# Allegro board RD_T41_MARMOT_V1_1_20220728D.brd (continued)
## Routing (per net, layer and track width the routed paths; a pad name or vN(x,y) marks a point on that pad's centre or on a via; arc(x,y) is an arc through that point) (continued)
VBAT: length 41.4
  TOP w0.254: R296.1 88.84,60.12 U25.1
  TOP w0.508: U25.1 88.83,62.13 C205.1 88.82,62.3 R295.2 83.08,63.34 v1(81.29,65.13)
  BOTTOM w0.381: BAT1.1 80.82,78.29 85.24,73.87 85.24,70.07 84.32,69.15 82.9,69.15 81.7,67.95 81.7,65.54 v1(81.29,65.13)
  BOTTOM w0.508: U27.8 72.19,75.11 C211.1 73.44,77.42 R303.2 77.42,77.43 BAT1.1
VBUS_5V:
  vias: v1(47.01,7.7) v1(47,6.97) v1(47.7,7.71) v1(47.7,6.98)
VCC_1V8: length 151.4
  TOP w0.254: 29.24,74.63 28.59,73.98 C24.1 26.37,73.98 R13.2 ; v1(15.84,66.2) 15.65,66.2 U8.3 14.97,64.44 R33.1
  TOP w0.381: v1(74.44,53.51) 73.82,54.14 v1(73.82,60.28) ; R36.1 111.45,31.46 103.09,31.46 95.85,38.7 Q1.1 91.07,41.39 84.6,41.39 R37.2 79.78,40.45 78.94,41.29 78.94,46.36 v1(79.07,46.49)
  TOP w0.635: v1(51.22,61.22) 41.03,71.41 41.03,75.76 39.21,77.58 35.3,77.58 J6.1
  BOTTOM w0.254: J6.1 25.78,76.14 v1(15.84,66.2)
  BOTTOM w0.381: 78.96,46.49 77.49,46.49 75.83,48.15 R30.1
  BOTTOM w0.508: Q3.2 55.22,58.02 55.77,58.57 69.11,58.57 70.83,60.28 v1(73.82,60.28) ; v1(74.44,53.51) 75.84,53.51 76.35,53.01 76.35,49.2 78.96,46.58 78.96,46.49 v1(79.07,46.49)
  BOTTOM w0.635: v1(51.22,61.22) 50.9,60.89 50.9,59.83 53.17,57.56 C204.1 53.74,58.02 Q3.2
VCC_3V3: length 163
  TOP w0.254: v1(76.13,13.38) 76.51,13.77 R215.1 ; R290.1 v1(117.67,56.69) 115.46,58.9 ; v1(82.65,18.99) R222.1 82.65,19.61 R232.1 ; R7.2 28.03,65 C13.1 28.92,64.99 29.7,65.77 ; v1(45.79,73.09) 45.79,67.46 50.86,62.39 v1(51,62.39) ; R288.2 107.45,93.68 109.68,91.44 ; R227.1 v1(86.23,18.87) ; v1(114.68,87.75) 114.1,87.75 R249.2 v1(110.98,88.43) ; v1(95.27,64.33) 94.39,64.33 D21.1 94.48,63.33 v1(95.3,63.33) ; R204.1 57.81,13.35 v1(57.48,13.68) ; v1(23.28,64.54) 16.33,71.49 R304.1 13.77,71.5 R297.1 11.78,72.54 v1(11.78,76.92) ; R301.2 v1(11.82,80.08) ; FB14.2 v1(83.79,5.02) ; R289.1 v1(117.68,52.43) ; U22.14 v1(81.22,18.64)
  TOP w0.292: R192.2 v1(105.06,34.3)
  TOP w0.381: v1(14.57,18.82) 23.78,28.04 R107.2 ; FB16.2 v1(21.6,60.63) ; J26.1 v1(118.39,52.13) ; FB13.2 v1(5.03,18.09)
  TOP w0.508: v1(61.87,14.84) 61.75,14.84 60.89,15.7 R24.2
  BOTTOM w0.254: R281.1 51.79,56.14 50.86,57.06 50.86,58.48 50.02,59.32 50.02,61.41 v1(51,62.39) ; R163.2 59.4,76.35 63.18,72.58 R307.2 67.71,72.57 R306.2 67.71,70.85 68.6,69.97 R305.2 ; v1(11.82,80.08) 12.32,79.58 12.32,77.46 v1(11.78,76.92) ; R314.1 76.72,13.82 R234.1 ; R314.1 76.36,13.38 v1(76.13,13.38) ; R314.1 77.72,12.82 R316.1 ; v1(114.68,87.75) 115.27,87.16 R257.2
  BOTTOM w0.381: v1(61.87,14.84) 62,14.71 R201.2 ; v1(81.22,18.64) 81.22,18.19 C181.1 80.94,17.91 C180.1 ; v1(5.03,18.09) 13.84,18.09 v1(14.57,18.82) C110.1 14.57,18.1 U10.1 13.42,16.36 R99.1 ; v1(117.67,56.69) 117.68,56.69 v1(117.68,52.43) 117.98,52.13 v1(118.39,52.13) ; v1(57.48,13.68) 57.48,13.88 58.21,14.61 R73.2
  BOTTOM w0.508: v1(48.86,77.64) FB12.1 48.64,76.94 46.79,75.09 FB11.1 45.96,73.26 v1(45.79,73.09) ; R236.2 v1(85.12,18.3) ; R201.2 v1(61.08,14.12) ; R163.2 v1(58.35,78.1)
  vias: v1(29.2,31.41) v1(29.55,32.02) v1(29.98,31.42) v1(33.69,65.73) v1(34.23,65.11) v1(34.69,65.73) v1(79.84,81.75) v1(79.84,80.75) v1(80.84,81.75) v1(80.84,80.75) v1(107.71,89.39) v1(108.66,88.43) v1(112.53,33.56) v1(112.52,32.87) v1(112.89,60.66) v1(113.42,60.05) v1(113.89,60.66) v1(114.42,60.05)
VCC_5V: length 34.5
  TOP w0.254: v1(36.66,11.94) R106.2 v1(35.88,12.71) ; C7.1 30.6,86.2 R2.1 29.66,85.25 27.6,85.25
  TOP w0.381: R25.2 50.27,30.52 v1(50.27,15.33) ; v1(107.7,72.05) R260.2 v1(106.89,71.23)
  TOP w0.508: R189.2 v1(77.67,93.06)
  BOTTOM w0.508: R207.2 57.05,10.36 ; R205.2 57.04,8.93 ; R202.2 57.15,7.44
  vias: v1(11.92,46.14) v1(11.98,47.13) v1(13,47.15) v1(24.25,85.14) v1(24.25,84.14) v1(25.25,85.14) v1(25.25,84.14) v1(26.25,85.14) v1(26.25,84.14) v1(27.93,35.21) v1(27.93,34.21) v1(45.01,13.45) v1(46.01,13.49) v1(46.9,13.48) v1(99.08,96.44) v1(99.46,97.12) v1(99.74,96.43)
VCC_12V: length 2.8
  TOP w0.254: R1.1 32.32,90.6 30.69,92.23
VCC_BAT: length 3.1
  TOP w0.254: BT1.1 99.75,32.53 R35.2
VCC_DDR: length 3.2
  BOTTOM w0.254: R12.2 87.05,62.52 C20.1 85.56,62.52 84.39,63.69
VCCQ_3V3: length 26
  TOP w0.203: v1(51.81,76.44) U12.P3 U12.N4 ; v1(50.81,76.45) U12.P5 U12.N4 ; U12.M4 U12.N4 ; U12.C6 v1(50.31,70.7)
  BOTTOM w0.254: R136.1 53.5,69.01 R133.1 52.57,69.01 R137.1 51.66,69.01 R134.1 50.75,69.01 R138.1 50.62,69.14 ; v1(50.31,70.7) 50.31,69.44 50.62,69.14 ; 50.62,69.14 49.61,69.14 R135.1
  BOTTOM w0.33: R141.1 50.29,75.69 48.28,75.69 47.87,75.28 47.87,74.3 48.34,73.83 49,73.83 49.33,73.5 49.33,72.99 49.1,72.76 49.1,71.32 49.72,70.7 v1(50.31,70.7)
  BOTTOM w0.381: R141.1 50.39,76.03 v1(50.81,76.45) 50.88,76.51 C116.1 ; C116.1 49.98,76.95 FB12.2 ; C116.1 51.86,76.95 C115.1 51.9,76.52 v1(51.81,76.44) 51.91,76.34 R142.2 ; R135.1 R139.1 47.68,69.02 R140.1
VDD5: length 3
  TOP w0.254: U21.4 v1(60.28,11.77)
  BOTTOM w0.508: R207.1 59.43,10.92 v1(60.28,11.77) 60.29,11.76 C168.1
VDD_RTC: length 9
  TOP w0.254: U6.L15 v1(67.61,46.86)
  BOTTOM w0.254: R294.1 73.41,45.24 73.41,45.78 72.23,46.96 70.46,46.96 69.7,46.2 C59.2 68.1,46.2 67.61,46.7 v1(67.61,46.86)
VDDIO18: length 4.6
  TOP w0.254: U6.N11 v1(65.01,45.56)
  BOTTOM w0.254: C192.2 65.02,45.56 v1(65.01,45.56) 64.57,45.12 R28.1
VDDIO18_DVP: length 3.3
  TOP w0.254: U6.K2 v1(59.16,47.51)
  BOTTOM w0.381: v1(59.16,47.51) 58.56,48.11 C95.1 57.49,48.48 R44.2
VDDIO33_1: length 3.8
  TOP w0.254: U6.C4 v1(59.81,52.71)
  BOTTOM w0.305: R64.1 59.78,54.79 59.78,53.8 C101.1 59.81,52.73 v1(59.81,52.71)
VDDIO33_2: length 44.6
  TOP w0.254: U6.J14 v1(66.96,48.16) ; U6.P9 v1(63.06,44.91)
  TOP w0.508: v1(77.63,47.09) 77.7,47.02 77.7,41.9 v1(76.74,40.95)
  BOTTOM w0.305: C102.1 67.14,47.98 67.14,47.98 v1(66.96,48.16)
  BOTTOM w0.381: C102.1 68.42,48.46 69.82,48.46 70.23,48.87 75.86,48.87 v1(77.63,47.09) ; v1(63.06,44.91) 62.78,44.63 62.78,43.91 C103.1 63.4,42.36 R63.1
  BOTTOM w0.508: R63.1 62.49,41.45 62.49,37.92 64.39,36.01 72.03,36.01 76.74,40.73 v1(76.74,40.95)
VDDIO_RTC: length 7.9
  TOP w0.254: U6.L17 68.83,47.18 v1(69.07,46.94)
  BOTTOM w0.254: v1(69.07,46.94) 69.91,46.94 70.33,47.37 72.52,47.37 R323.1 74.2,45.76 C191.2
VDDMEM: length 3.2
  TOP w0.254: U6.E6 v1(61.76,51.41) U6.E7 ; U6.E12 v1(65.66,51.41) ; U6.E11 v1(64.36,51.41) U6.E10 ; U6.E8 v1(63.06,51.41) U6.E9
  vias: v1(71.78,58.65) v1(72.48,59.44) v1(72.48,58.64)
VDDMSC0: length 16.2
  TOP w0.292: R194.1 v1(105.01,35.42) ; R195.1 v1(105.02,43.12) ; R196.1 v1(105.03,42.02) ; R193.1 v1(105,36.5) ; R197.1 v1(105.03,40.91)
  TOP w0.305: v1(105,39.56) 108.15,39.56 108.4,39.81 J16.4
  BOTTOM w0.305: v1(105.01,35.42) 105.01,36.5 v1(105,36.5) v1(105,39.56) 105,40.89 v1(105.03,40.91) 105.03,42.01 v1(105.03,42.02) 105.03,43.11 v1(105.02,43.12)
  vias: v1(111.64,39.81) v1(112.38,39.81)
ADC0: length 38.4
  TOP w0.102: R35.1 99.25,34.08 C87.1 98.29,34.09 R40.2 97.32,34.09 TP14.1 94.06,31.96 91.21,31.96 89.6,33.57 82.38,33.57 71.7,44.25 71.63,44.32 69.28,44.32 68.68,44.92 67.6,44.92 U6.P15
ADC1: length 49.2
  TOP w0.102: R36.2 110.67,29.7 C88.1 108.54,29.71 R41.2 TP17.1 104.9,28.54 94.12,28.54 89.41,33.26 82.36,33.26 71.54,44.08 69.09,44.08 U6.R17
ADC2: length 32.7
  TOP w0.102: U6.P16 68.42,45.23 68.52,45.14 68.82,45.14 69.36,44.6 71.65,44.6 82.39,33.86 TP15.1 91.32,33.85 C89.1 92.59,33.85 R42.2 93.76,34.03 Q1.2
ADC3: length 23.3
  TOP w0.102: R39.2 87.15,37.65 C90.1 83.64,37.66 TP16.1 78.95,37.66 72.36,44.25 71.76,44.85 69.48,44.85 68.94,45.39 68.68,45.39 68.52,45.55 67.62,45.55 U6.N15
ADC_AVDD: length 4.3
  TOP w0.254: v1(69.47,45.76) 69.35,45.88 U6.N17 U6.N16
  BOTTOM w0.254: v1(69.47,45.76) 69.55,45.84 C72.1 71.21,45.84 C71.1 72.18,45.84 FB7.2
AK7755_AVDD: length 11.1
  TOP w0.254: R191.2 55.19,84.99 U20.1 ; U17.36 v1(61.59,85.35) ; U17.21 v1(67.57,80.38)
  TOP w0.381: 56.94,86.42 C157.1
  TOP w0.508: C157.1 v1(57.76,86.36) ; U20.1 56.94,86.42
  BOTTOM w0.254: C140.1 61.62,85.32 v1(61.59,85.35) ; C141.1 67.15,79.96 v1(67.57,80.38)
  BOTTOM w0.508: 61.41,85.8 58.32,85.8 v1(57.76,86.36)
AK7755_AVDD2: length 3.7
  TOP w0.254: U17.29 v1(65.09,85.35)
  BOTTOM w0.254: C138.1 64.51,84.77 v1(65.09,85.35) 65.4,85.04 C137.1 65.4,84.62 FB17.1
AK7755_AVDRV: length 1.5
  TOP w0.254: U17.24 v1(67.57,81.88)
  BOTTOM w0.254: C134.1 67.54,81.9 v1(67.57,81.88)
AK7755_IOVDD: length 12.2
  TOP w0.249: R174.2 v1(71.13,78)
  TOP w0.254: U17.12 v1(62.59,77.17)
  TOP w0.33: R169.1 v1(67.45,74.6) ; R168.1 v1(66.54,74.59)
  TOP w0.381: v1(71.62,81.97) 71,81.97 R166.2 71.23,81.35 v1(71.63,81.35) 71.63,81.14 R171.2 ; R172.2 57.04,82.37 v1(57.03,82.38)
  BOTTOM w0.381: v1(57.03,82.38) 57.03,81.99 R163.1
AK7755_LDOE: length 2.8
  TOP w0.249: U17.23 68.89,81.38 R166.1
AK7755_LIN: length 1.3
  TOP w0.102: TP50.1 59.77,88.04 C130.1
AK7755_PDN: length 2.4
  TOP w0.102: R173.1 70.11,80.67 R171.1 71.05,80.66 R83.1
AK7755_VCOM: length 1.9
  TOP w0.254: v1(59.62,83.52) 59.77,83.38 U17.1
  BOTTOM w0.254: v1(59.62,83.52) 60.21,82.94 C135.1
BOOTSEL0: length 80.4
  TOP w0.102: v1(36.51,61.88) 36.14,61.5 25.78,61.5 18.65,68.63 13.27,68.63 D23.2 ; D23.2 12.56,69.31 SW4.3 SW4.4 ; D23.2 12.58,70.22 R297.2 ; U6.A9 63.47,53.76 63.47,62.45 62.85,63.07 v1(62.85,66.59)
  BOTTOM w0.102: v1(36.51,61.88) 36.51,62.23 39.22,64.94 61.2,64.94 v1(62.85,66.59)
BOOTSEL1: length 86.9
  TOP w0.102: v1(35.81,61.9) 25.95,61.9 23.71,64.15 23.71,64.64 13.69,74.66 D24.1 13.57,77.95 R300.2 12.15,77.59 SW5.3 SW5.4 ; U6.B9 63.39,53.16 63.7,53.47 63.7,62.61 63.17,63.14 63.17,66.13 63.34,66.31 63.34,66.98 v1(62.9,67.42)
  BOTTOM w0.102: v1(62.9,67.42) 62.5,67.02 62.5,66.62 61.04,65.17 39.07,65.17 v1(35.81,61.9)
BT656_D0_PD00: length 26.4
  TOP w0.102: R254.2 v1(111.8,80.39)
  BOTTOM w0.102: J23.5 104.82,101.38 104.82,99.69 112.22,92.29 112.22,80.82 v1(111.8,80.39)
BT656_D1_PD01: length 24.2
  TOP w0.102: R256.2 v1(111.8,79.38)
  BOTTOM w0.102: v1(111.8,79.38) 112.54,80.12 112.54,92.41 105.98,98.97 J23.6
BT656_D2_PD02: length 27.8
  TOP w0.102: R259.2 v1(111.8,78.36)
  BOTTOM w0.102: J23.7 107.51,101.52 107.51,97.85 112.78,92.57 112.78,79.34 v1(111.8,78.36)
BT656_D3_PD03: length 25.6
  TOP w0.102: R263.2 v1(111.8,77.34)
  BOTTOM w0.102: J23.8 108.52,97.23 113.07,92.68 113.07,78.62 v1(111.8,77.34)
BT656_D4_PD04: length 29.2
  TOP w0.102: R264.2 v1(111.8,76.33)
  BOTTOM w0.102: v1(111.8,76.33) 113.34,77.87 113.34,92.8 110.07,96.07 110.07,101.55 J23.9
BT656_D5_PD05: length 27
  TOP w0.102: R268.2 v1(111.8,75.31)
  BOTTOM w0.102: v1(111.8,75.31) 113.56,77.07 113.56,93.15 111.06,95.65 J23.10
BT656_D6_PD06: length 30.7
  TOP w0.102: R270.2 v1(111.8,74.29)
  BOTTOM w0.102: v1(111.8,74.29) 113.78,76.28 113.78,93.36 112.43,94.71 112.43,101.36 J23.11
BT656_D7_PD07: length 28.4
  TOP w0.102: R272.2 v1(111.8,73.28)
  BOTTOM w0.102: v1(111.8,73.28) 114.02,75.51 114.02,99.57 J23.12
BT656_PCLK_PD08: length 25.2
  TOP w0.102: R274.2 v1(111.8,81.41)
  BOTTOM w0.102: J23.3 104.59,101.39 104.59,99.54 111.8,92.33 v1(111.8,81.41)
CLK_CTRL: length 2.6
  TOP w0.102: R232.2 82.22,18.99 v1(82.22,18.54) U22.12
  BOTTOM w0.102: R233.1 81.9,18.21 v1(82.22,18.54)
CLKO: length 2.9
  TOP w0.102: U17.9 60.09,79.38 59.22,78.51 TP54.1
CODEC_AVDD: length 5
  TOP w0.254: U6.R1 v1(57.86,44.26)
  BOTTOM w0.381: v1(57.86,44.26) 56.31,44.26 55.76,43.71 C61.1 55.65,43.7 C62.1 53.79,43.7 FB6.2
CORE_0V8: length 12
  TOP w0.254: U6.H12 v1(65.66,49.46) U6.H13 ; U6.M5 v1(61.11,46.21) U6.M6 ; U6.N10 v1(64.36,45.56) ; U6.H9 v1(63.06,49.46) U6.H8 ; U6.N9 v1(63.06,45.56) U6.N8 ; U6.H11 v1(64.36,49.46) U6.H10 ; U6.N7 v1(61.76,45.56) U6.N6 ; U6.J5 v1(60.46,48.81) U6.H5 ; U6.K13 v1(66.31,48.16) U6.J13 ; U6.H6 v1(61.76,49.46) U6.H7 ; U6.K5 v1(60.46,47.51) U6.L5
  TOP w0.381: TP4.1 77.12,54.98 J4.2
  vias: v1(71.7,54.96) v1(71.7,54.16) v1(72.5,54.96) v1(72.5,54.16)
CSI_CLKN_DVP_D4: length 19.1
  TOP w0.102: U6.M2 58.77,46.6 57.56,46.6 57.12,46.16 48.65,46.16 48.03,45.54 48.03,45.37 48.09,45.31 48.09,45.14 47.97,45.03 47.8,45.03 47.74,45.08 47.57,45.08 47.45,44.96 47.45,44.79 47.54,44.71 47.54,44.54 47.42,44.42 47.25,44.42 47.17,44.51 47,44.51 46.77,44.28 45.61,44.28 TP39.1 45.06,44.28 42.33,44.28 42.22,44.18 R119.1
CSI_CLKP_DVP_D5: length 19
  TOP w0.102: U6.L3 59.18,46.87 57.44,46.87 57,46.44 48.53,46.44 46.66,44.56 45.61,44.56 TP38.1 45.06,44.56 42.35,44.56 42.22,44.68 R116.1
CSI_DATAN0_DVP_D0: length 17.5
  TOP w0.102: U6.L2 58.61,47.18 58.29,47.51 57.32,47.51 56.96,47.15 45.61,47.15 TP34.1 45.05,47.15 42.37,47.15 42.22,47.29 R110.1
CSI_DATAN1_DVP_D2: length 19.8
  TOP w0.102: U6.N1 58.16,45.91 57.6,45.91 57.15,45.47 50.36,45.47 49.73,44.84 49.73,44.67 49.44,44.39 49.27,44.39 49.16,44.27 49.16,44.1 49.24,44.01 49.24,43.84 49.12,43.72 48.95,43.72 48.87,43.81 48.7,43.81 48.58,43.69 48.58,43.52 48.67,43.44 48.67,43.27 48.55,43.15 48.38,43.15 48.29,43.24 48.12,43.24 48.01,43.12 48.01,42.95 48.09,42.86 48.09,42.69 47.97,42.57 47.8,42.57 47.72,42.66 47.55,42.66 46.65,41.76 45.61,41.76 TP37.1 45.05,41.76 42.33,41.76 42.22,41.66 R114.1
CSI_DATAP0_DVP_D1: length 17.5
  TOP w0.102: R108.1 42.22,46.73 42.36,46.87 45.05,46.87 TP31.1 45.61,46.87 46.02,46.87 46.14,46.75 46.14,46.47 46.26,46.35 46.42,46.35 46.54,46.47 46.54,46.75 46.66,46.87 57.08,46.87 57.44,47.23 58.14,47.23 U6.L1
CSI_DATAP1_DVP_D3: length 19.8
  TOP w0.102: R112.1 42.22,42.18 42.36,42.04 45.05,42.04 TP36.1 45.61,42.04 46.53,42.04 50.24,45.75 57.04,45.75 57.48,46.19 59.14,46.19 U6.M3
CSI_VCC08: length 5.8
  TOP w0.203: U6.N2 58.7,45.88 58.33,45.52 57.67,45.52 56.95,44.8 v1(56.75,44.8)
  BOTTOM w0.381: v1(56.75,44.8) 55.78,44.8 C92.1 54.63,44.55 C91.1 54.62,44.56 53.75,44.56 FB9.1
CSI_VCC18: length 4.2
  TOP w0.254: U6.K3 v1(59.81,47.51)
  BOTTOM w0.381: v1(59.81,47.51) 59.81,47.43 59.43,47.05 C94.1 58.54,46.89 C93.1 58.05,47.36 FB10.1
D_RX: length 2.2
  TOP w0.102: R292.1 117.79,54.13 J26.3
D_TX: length 2.2
  TOP w0.102: R293.1 117.69,55.13 J26.4
DDR_VREF: length 5.8
  TOP w0.254: U6.E5 v1(60.46,51.41)
  BOTTOM w0.254: v1(60.46,51.41) 58.78,51.41 58.36,51.82 C54.1 57.07,51.82 R22.2 57.01,51.77 R19.1 57.02,51.02 C50.2
DDRPLL_VCCA: length 3.2
  TOP w0.254: U6.B8 v1(63.06,53.36)
  BOTTOM w0.381: v1(63.06,53.36) 63.02,53.32 C52.1 62.18,53.32 C51.1 62.18,54.97 FB1.2
DDRVDD: length 5.8
  TOP w0.254: U6.F10 v1(64.36,50.76) U6.F11 ; U6.F7 v1(61.76,50.76) U6.F6 ; U6.F9 v1(63.06,50.76) U6.F8 ; U6.F12 v1(65.66,50.76) ; U6.F5 v1(60.46,50.76)
  BOTTOM w0.254: R19.2 57.02,49.98 C50.1 58.02,49.98 C53.1
  vias: v1(71.87,57.14) v1(72.48,57.56) v1(72.48,56.76)
DMIC_CLK_PB28: length 244.3
  TOP w0.102: R147.2 v1(88.85,7.28) ; v1(43.72,58.73) 42.1,60.35 23.14,60.35 21.22,58.43 17.12,58.43 R157.2 16.44,58.45 9.08,51.09 9.08,14.56 7.51,12.99 R144.2 v1(6.24,12.99) ; v1(64.57,65.67) 65.01,65.67 R153.2 65.15,67.17 66.14,68.15 74.58,68.15 92.2,85.78 101.62,85.78 102.47,86.64 R154.2
  BOTTOM w0.102: v1(88.85,7.28) 88.37,6.81 86.54,6.81 81.36,1.63 56.6,1.63 54.46,3.77 52.03,3.77 51.53,3.27 47.38,3.27 46.89,3.77 44.42,3.77 43.87,3.22 14.6,3.22 6.56,11.25 6.56,12.66 v1(6.24,12.99) ; v1(64.57,65.67) 62.9,65.67 61.75,64.52 49.36,64.52 43.72,58.88 v1(43.72,58.73)
DMIC_DAT0_PB29: length 201.2
  TOP w0.102: R148.2 v1(88.01,7.29) ; R321.2 v1(68.04,62.36) ; R145.2 v1(6.25,13.84)
  BOTTOM w0.102: 88.01,7.29 87.85,7.45 77.37,7.45 74.89,9.93 74.89,19.89 69.52,25.26 69.52,32.45 68.36,33.61 52.05,33.61 47.23,38.44 47.23,60.53 50.29,63.59 66.42,63.59 67.65,62.36 v1(68.04,62.36) ; 88.01,7.29 87.77,7.05 86.44,7.05 81.25,1.87 56.73,1.87 54.6,4 51.92,4 51.44,3.51 47.49,3.51 47,4 44.36,4 43.79,3.42 14.74,3.42 6.79,11.37 6.79,13.3 v1(6.25,13.84) ; 88.01,7.29 v1(88.01,7.29)
DMIC_DAT1_PB30: length 100.3
  TOP w0.102: R322.2 v1(67.08,66.3) 68.66,67.88 74.63,67.88 92.28,85.53 101.99,85.53 103.29,86.84 R155.2 ; R158.2 17.68,58.67 21.1,58.67 23.03,60.6 42.45,60.6 v1(43.6,59.45)
  BOTTOM w0.102: v1(67.08,66.3) 66.67,65.89 65.35,65.89 65.17,66.07 62.84,66.07 61.5,64.73 49.08,64.73 43.8,59.45 v1(43.6,59.45)
DRV_VBUS: length 77.7
  TOP w0.102: v1(43.85,8.91) 43.85,14.74 47.09,17.98 47.09,30.97 51.16,35.03 v1(51.16,35.08) ; R55.2 v1(66.13,62.37)
  BOTTOM w0.102: v1(43.85,8.91) R38.2 43.78,9.38 U9.4 ; v1(66.13,62.37) 65.41,63.09 50.79,63.09 48.1,60.4 48.1,38.14 v1(51.16,35.08)
DVP_D0: length 39.2
  TOP w0.102: v1(43.1,51.6) 41.12,51.6 40.23,52.49 34.07,52.49 30.99,49.41 30.99,43.65 21.91,34.57 J11.11 ; R111.2 v1(43.84,47.63)
  BOTTOM w0.102: v1(43.1,51.6) 43.84,50.86 v1(43.84,47.63)
DVP_D1: length 43.8
  TOP w0.102: v1(41.65,51.96) 41.22,51.96 40.34,52.83 34,52.83 30.73,49.56 30.73,43.71 22.09,35.07 J11.12 ; R109.2 v1(43.84,46.38)
  BOTTOM w0.102: v1(41.65,51.96) 43.28,51.96 44.21,51.03 44.21,46.74 v1(43.84,46.38)
DVP_D2: length 48.1
  TOP w0.102: v1(41.8,53.16) 41.73,53.09 33.86,53.09 30.48,49.71 30.48,43.82 22.23,35.57 J11.13 ; R115.2 v1(43.84,41.28)
  BOTTOM w0.102: v1(43.84,41.28) 45.21,42.64 45.21,51.56 43.6,53.16 v1(41.8,53.16)
DVP_D3: length 49.3
  TOP w0.102: J11.14 22.38,36.07 30.23,43.93 30.23,49.81 33.76,53.34 40.97,53.34 v1(41.11,53.47) ; R113.2 v1(43.84,42.52)
  BOTTOM w0.102: v1(41.11,53.47) 41.11,53.34 41.65,52.8 43.63,52.8 44.99,51.44 44.99,43.67 v1(43.84,42.52)
DVP_D4: length 47.5
  TOP w0.102: R119.2 v1(43.84,43.77) ; v1(40.62,53.72) 40.49,53.6 33.66,53.6 29.98,49.92 29.98,43.98 23.07,37.07 J11.16
  BOTTOM w0.102: v1(40.62,53.72) 40.62,53.35 41.39,52.58 43.44,52.58 44.73,51.29 44.73,44.66 v1(43.84,43.77)
DVP_D5: length 42.9
  TOP w0.102: J11.17 23.25,37.57 29.69,44.01 29.69,50.04 33.64,53.98 v1(39.62,53.98) ; R117.2 v1(43.84,45.06)
  BOTTOM w0.102: v1(43.84,45.06) 44.48,45.7 44.48,51.15 43.3,52.33 41.28,52.33 v1(39.62,53.98)
DVP_D6: length 54.7
  TOP w0.102: U6.H2 58.72,49.25 57.46,49.25 56.64,48.43 47.05,48.43 41.06,54.41 33.69,54.41 29.42,50.15 29.42,44.21 23.28,38.07 J11.18
DVP_D7: length 52.6
  TOP w0.102: U6.H3 59.16,49.46 57.33,49.46 56.55,48.69 47.1,48.69 41.12,54.67 33.61,54.67 33.52,54.58 33.52,54.58 29.18,50.25 29.18,44.34 23.42,38.57 J11.19
DVP_D8: length 50.9
  TOP w0.102: J11.21 24.06,39.57 28.93,44.45 28.93,50.35 33.51,54.92 41.22,54.92 47.21,48.94 56.49,48.94 57.33,49.78 U6.G1
DVP_D9: length 54.3
  TOP w0.102: U6.G2 58.71,49.78 58.4,50.09 57.3,50.09 56.4,49.19 47.28,49.19 41.3,55.18 33.39,55.18 30.27,52.06 30.27,52.06 28.67,50.46 28.67,44.54 24.2,40.07 J11.22
DVP_D10: length 52.2
  TOP w0.102: J11.23 24.36,40.57 28.42,44.63 28.42,50.56 30.01,52.16 30.01,52.16 33.28,55.43 41.4,55.43 47.39,49.45 56.32,49.45 57.19,50.31 58.51,50.31 58.71,50.11 59.16,50.11 U6.G3
DVP_D11: length 54
  TOP w0.102: J11.24 24.52,41.07 28.21,44.76 28.21,50.65 29.81,52.25 33.25,55.7 41.46,55.7 47.47,49.69 56.24,49.69 57.08,50.53 58.74,50.53 U6.F2
DVP_HSYNC: length 55.9
  TOP w0.102: J11.8 21.16,33.07 31.45,43.36 31.45,49.12 34.34,52.01 38.81,52.01 40.17,50.65 40.81,50.65 TP33.1 41.35,50.55 41.73,50.92 43.77,50.92 46.74,47.95 56.82,47.95 57.67,48.8 58.33,48.8 58.65,48.48 U6.J2
DVP_MCLK_PA15: length 27.9
  TOP w0.102: R126.2 TP30.1 32.81,57.45 26.54,51.18 26.54,46.18 23.43,43.07 J11.28
DVP_PCLK: length 54.2
  TOP w0.102: J11.26 23.28,42.07 27.34,46.13 27.34,50.94 32.91,56.51 41.99,56.51 42.79,55.71 TP32.1 44.09,54.41 44.09,54.41 48.58,49.92 56.12,49.92 56.95,50.75 59.17,50.75 U6.F3
DVP_VSYNC: length 52.9
  TOP w0.102: J11.9 21.24,33.57 31.22,43.55 31.22,49.3 34.18,52.26 39.53,52.26 TP35.1 40.55,51.24 43.8,51.24 46.86,48.18 56.72,48.18 57.59,49.04 58.47,49.04 58.71,48.81 59.16,48.81 U6.J3
E_MICBIAS_2V5: length 24.4
  TOP w0.305: R182.2 v1(59.06,97.88)
  TOP w0.381: v1(49.64,97.78) R184.2 48.95,96.54 48.95,87.89 C156.1 50.43,86.42 U20.5
  BOTTOM w0.254: v1(49.64,97.78) 50.06,97.36 50.82,97.36 51.12,97.66 58.84,97.66 v1(59.06,97.88)
EC_CLK: length 9.9
  TOP w0.102: U6.A1 58.19,54.55 55.69,57.05 55.69,61.06 R45.2 55.21,62.31 R65.2
EC_CMD: length 13.2
  TOP w0.102: U6.C3 59.17,52.7 58.72,52.7 58.52,52.9 58.52,53.2 58.36,53.36 58.03,53.36 57.86,53.52 57.86,54.2 57,55.06 56.12,55.06 54.42,56.76 54.42,61.06 R309.1 53.94,62.3 R66.2
EC_D0: length 10.3
  TOP w0.102: R69.2 56.43,62.32 R311.1 56.91,61.07 56.91,56.99 58.52,55.39 58.52,53.57 58.84,53.25 U6.B2
EC_D1: length 9.2
  TOP w0.102: U6.A2 58.84,55.53 57.92,56.45 57.92,61.13 R318.1 57.48,61.57 R70.2
EC_D2: length 13.6
  TOP w0.102: U6.C2 58.64,52.38 58.33,52.69 57.78,52.69 57.2,53.27 57.2,53.86 56.68,54.38 55.89,54.38 53.11,57.16 53.11,59.08 52.55,59.64 52.55,61.03 R319.1 52.06,61.53 R71.2
EC_D3: length 12.2
  TOP w0.102: R74.2 53.01,62.3 R320.1 53.49,61.04 53.49,59.69 53.93,59.24 53.93,56.7 55.94,54.7 56.86,54.7 57.5,54.06 57.5,53.35 57.81,53.03 U6.B1
EFUSE_AVDD: length 2.7
  TOP w0.254: U6.D4 v1(59.81,52.06)
  BOTTOM w0.305: R324.1 59.26,53.76 59.26,52.61 v1(59.81,52.06)
EFUSE_AVDD18: length 2.9
  BOTTOM w0.33: Q3.3 58.09,56.11 R282.2 58.89,55.65 R324.2
EFUSE_EN: length 20
  TOP w0.102: R79.1 v1(60.97,62.05)
  BOTTOM w0.102: Q3.1 54.41,56.14 R281.2 52.61,56.75 51.62,56.75 51.16,57.21 51.16,58.61 50.38,59.39 50.38,61.25 51.59,62.46 60.56,62.46 v1(60.97,62.05)
EMMC_3V3: length 7
  TOP w0.203: U12.F5 v1(50.36,71.76) 50.31,71.72 U12.E6
  TOP w0.254: U12.J10 48.77,73.26 v1(48.81,73.3) U12.K9
  TOP w0.33: v1(48.81,73.3) 48.81,73.25 50.3,71.76 v1(50.36,71.76)
  BOTTOM w0.254: C114.1 50.41,71.71 v1(50.36,71.76)
  BOTTOM w0.33: FB11.2 47.89,72.92 C117.1 48.63,72.62 48.63,73.12 v1(48.81,73.3)
EMMC_CLK: length 17
  TOP w0.102: R65.1 55.52,63.65 55.52,68.27 54.85,68.94 v1(54.85,72.41) ; U12.M6 v1(49.82,74.27)
  BOTTOM w0.102: v1(54.85,72.41) 51.21,72.41 50.74,72.88 50.74,73.39 49.86,74.27 v1(49.82,74.27) 49.46,74.63 C119.1
EMMC_CMD: length 15.9
  TOP w0.102: v1(54,73.71) 54,68.65 54.95,67.7 54.95,64.35 R66.1 ; U12.M5 50.81,74.28 v1(50.74,74.21)
  BOTTOM w0.102: R141.2 50.39,74.57 v1(50.74,74.21) 51.24,73.71 v1(54,73.71)
EMMC_D0: length 10.1
  TOP w0.102: v1(53.36,67.38) 53.25,67.38 51.81,68.82 U12.A3 ; v1(56.24,67.03) 56.24,63.55 R69.1
  BOTTOM w0.102: R133.2 53.5,67.51 v1(53.36,67.38) 53.83,66.91 56.12,66.91 v1(56.24,67.03)
EMMC_D1: length 11.4
  TOP w0.102: v1(51.51,67.38) 51.51,68.12 51.31,68.31 U12.A4 ; v1(56.64,66.26) 56.64,64.21 R70.1
  BOTTOM w0.102: v1(56.64,66.26) 56.33,66.57 52.32,66.57 v1(51.51,67.38) 51.66,67.53 R134.2
EMMC_D2: length 8.2
  TOP w0.102: R71.1 52.06,63.55 49.65,65.95 v1(49.65,67.38) 50.09,67.81 50.25,67.81 50.81,68.38 U12.A5
  BOTTOM w0.102: v1(49.65,67.38) 49.48,67.55 R135.2
EMMC_D3: length 8.9
  TOP w0.081: 52.06,69.04 52.06,69.51 U12.B2
  TOP w0.102: R74.1 54.29,64.62 v1(54.29,67.38) 53.29,68.38 52.72,68.38 52.06,69.04
  BOTTOM w0.102: v1(54.29,67.38) 54.41,67.49 R136.2
EMMC_D4: length 3.5
  TOP w0.081: U12.B3 51.56,69.51 51.56,68.55 51.78,68.33
  TOP w0.102: v1(52.43,67.38) 52.43,67.68 51.78,68.33
  BOTTOM w0.102: v1(52.43,67.38) 52.57,67.51 R137.2
EMMC_D5: length 3.4
  TOP w0.081: 51.07,68.99 51.07,69.51 U12.B4
  TOP w0.102: 51.07,68.99 51.07,68.15 50.58,67.67 v1(50.58,67.38)
  BOTTOM w0.102: v1(50.58,67.38) 50.75,67.54 R138.2
EMMC_D6: length 4.3
  TOP w0.081: U12.B5 50.56,69.51 50.56,68.59 50.15,68.18
  TOP w0.102: v1(48.73,67.38) 49.53,68.18 50.15,68.18
  BOTTOM w0.102: R139.2 48.59,67.51 v1(48.73,67.38)
EMMC_D7: length 4.4
  TOP w0.081: U12.B6 50.06,69.51 50.06,69.13 50.03,69.1
  TOP w0.102: 50.03,69.1 49.45,68.52 48.94,68.52 v1(47.8,67.38)
  BOTTOM w0.102: R140.2 47.68,67.5 v1(47.8,67.38)
EMMC_DS: length 1.6
  TOP w0.102: U12.H5 50.09,72.76 v1(49.98,72.87)
  BOTTOM w0.102: TP47.1 49.71,72.6 v1(49.98,72.87)
EMMC_RST: length 3.5
  TOP w0.102: U12.K5 50.88,73.76 v1(51.33,74.21)
  BOTTOM w0.102: R76.2 52.8,74.83 C118.1 51.92,74.81 R142.1 51.91,74.78 v1(51.33,74.21)
EMMC_VDDI: length 3.2
  TOP w0.081: 53.27,70.31 53.06,70.51 52.57,70.51 U12.C2 52.56,70.01 53.23,70.01 53.27,70.05
  TOP w0.089: 53.27,70.31 v1(53.4,70.18) 53.27,70.05
  BOTTOM w0.254: C120.1 53.43,70.21 v1(53.4,70.18)
EN_DLDO: length 7.1
  TOP w0.102: R60.1 70.54,38.17 R61.1 70.54,40.66 69.9,41.3 68.88,41.3 67.29,42.9 U6.U15
EXCLKI: length 6.9
  TOP w0.102: U6.C1 57.15,52.38 56.04,53.49 55.18,53.49 R31.2 53.77,53.01 Y2.1 52.83,53.96 C69.2
EXCLKO: length 4.6
  TOP w0.102: U6.D2 58.52,52.05 56.99,52.05 56.03,53.01 R31.1 R32.2
GMAC_MDC: length 29.3
  TOP w0.102: R49.2 65.18,37.02 65.18,31 77.86,18.32 77.86,15.06 78.22,14.7 U22.22
GMAC_MDIO: length 33.2
  TOP w0.102: U22.23 78.18,14.2 R215.2 77.74,14.53 77.43,14.84 77.43,18.16 64.42,31.17 64.42,38.67 R51.2
GMAC_NRST_PB28: length 86.4
  TOP w0.102: R156.1 v1(65.15,62.37) ; R287.2 v1(69.29,33.35)
  BOTTOM w0.102: R298.1 75.19,17.13 75.19,20.12 69.92,25.39 69.92,32.72 v1(69.29,33.35) 68.77,33.87 52.88,33.87 48.32,38.43 48.32,60.26 50.86,62.8 64.72,62.8 v1(65.15,62.37)
GMAC_PHY_CLK: length 47
  TOP w0.102: U22.31 83.22,9.61 82.08,8.47 76.51,8.47 74.01,10.97 74.01,19.72 63.4,30.33 63.4,38.12 63.85,38.57 R47.2
GMAC_RXD0: length 32.6
  TOP w0.102: R220.1 83.59,21.53 79.69,21.53 68.53,32.68 68.53,40.58 65.99,43.13 U6.U13
GMAC_RXD1: length 33.9
  TOP w0.102: U6.R12 65.68,44.24 65.68,42.99 68.22,40.44 68.22,32.5 79.51,21.22 80.19,21.22 R223.1 81.14,21.14 82.12,21.14 R222.2 83.54,20.61 R221.1
GMAC_RXDV: length 43.6
  TOP w0.102: R218.1 80.31,9.83 78.09,9.83 77.65,10.27 75.94,10.27 74.89,11.33 74.89,20.12 64.15,30.85 64.15,38.77 64.42,39.04 64.42,40.8 63.69,41.52 63.69,42.98 U6.U9
GMAC_TXCLK: length 30.8
  TOP w0.102: U6.T12 65.47,43.8 65.47,42.75 67.9,40.32 67.9,38.81 67.42,38.33 67.42,31.77 R212.1
GMAC_TXD0: length 27.3
  TOP w0.102: U22.16 79.96,17.9 66.68,31.18 66.68,38.19 67.26,38.77 R52.2
GMAC_TXD1: length 25.5
  TOP w0.102: R53.2 66.28,37.09 66.28,31.06 79.52,17.82 U22.17
GMAC_TXEN: length 29.9
  TOP w0.102: R48.2 66.18,39.05 65.5,38.37 65.5,31.22 78.28,18.44 78.28,16.39 78.96,15.7 U22.20
HPOUTL: length 40.9
  TOP w0.203: U6.T1 40.9,26.65 35.25,26.65 30.63,22.02 C112.2
I2C0_MIPI_DVP_SCK: length 55.7
  TOP w0.102: U6.J4 59.83,48.17 57.65,48.17 56.91,47.44 46.57,47.44 44.57,49.44 v1(42.75,49.44) ; TP41.1 42.45,39.02 v1(41.89,39.02) J12.20 29.18,39.02 20.73,30.57 J11.3
  BOTTOM w0.102: v1(41.89,39.02) 42.72,39.85 42.72,49.41 v1(42.75,49.44)
I2C0_MIPI_DVP_SDA: length 57.6
  TOP w0.102: v1(42.41,50.28) 42.74,50.61 43.71,50.61 46.66,47.66 56.85,47.66 57.67,48.48 U6.J1 ; J11.6 21.86,32.07 29.09,39.3 33.82,39.3 34.05,39.52 J12.19 37.67,39.52 37.86,39.32 40.94,39.32 v1(41.14,39.52) 41.26,39.41 42.44,39.41 TP40.1
  BOTTOM w0.102: v1(41.14,39.52) 42.29,40.68 42.29,50.16 v1(42.41,50.28)
I2C1_SCK_CODEC: length 4.3
  TOP w0.102: U17.18 65.59,77.2 66.03,76.76 66.93,76.76 R169.2 67.46,76.24 R88.1
I2C1_SCK_RTC: length 26.6
  TOP w0.102: U6.C10 63.71,52.71 63.71,53.15 63.91,53.34 63.91,62.74 63.41,63.24 63.41,64.57 63.58,64.74 63.58,67.87 68.58,72.86 69.51,72.86 v1(69.8,72.58)
  BOTTOM w0.102: R307.1 v1(69.8,72.58) 70.96,72.58 U27.6
I2C1_SDA_CODEC: length 3.2
  TOP w0.102: U17.17 65.09,76.73 65.58,76.23 R86.1 66.53,76.23 R168.2
I2C1_SDA_RTC: length 24.1
  TOP w0.102: U6.C11 64.34,52.73 64.34,62.96 64.18,63.13 64.18,67.63 67.22,70.67 v1(68.76,70.67)
  BOTTOM w0.102: v1(68.76,70.67) 68.76,71.3 ; 68.76,71.3 U27.5 ; 68.76,71.3 R306.1
I2C2_SID: length 5
  TOP w0.102: U17.20 68.81,79.88 R175.2 69.53,80.16 70.62,80.16 R174.1
I2S_DAC_BCLK: length 27.6
  TOP w0.102: U6.B4 59.86,53.31 59.86,65.04 58.9,66 58.9,75 57.46,76.45 57.46,79.24 R160.1
I2S_DAC_BCLK_PC15: length 2
  TOP w0.102: U17.8 59.14,79.88 R160.2
I2S_DAC_LRCK: length 28.3
  TOP w0.102: U6.A3 59.49,64.39 58.16,65.72 58.16,74.64 56.58,76.22 56.58,79.3 R159.1
I2S_DAC_LRCK_PC16: length 1.8
  TOP w0.102: R159.2 58.71,80.38 U17.7
I2S_DAC_MCLK: length 10.5
  TOP w0.102: R77.1 59.77,73.08 62.09,75.41 U17.11
I2S_SDTI: length 24.1
  TOP w0.102: U6.B5 60.79,53.2 60.43,53.56 60.43,64.94 60.68,65.19 60.68,69.53 64.36,73.21 64.36,74.98 R161.1
I2S_SDTI_PC18: length 2
  TOP w0.102: R161.2 U17.16
I2S_SDTO: length 31.9
  TOP w0.102: R164.1 56.08,81.44 55.5,80.86 55.5,76.03 57.34,74.18 57.34,66 59.18,64.17 59.18,53.34 U6.B3
I2S_SDTO_PC17: length 2
  TOP w0.102: U17.4 59.15,81.88 R164.2
I_MICBIAS_2V5: length 2.6
  BOTTOM w0.381: R93.2 14.58,11.66 C109.1 14.58,13.35 U10.5
IM0: length 4
  TOP w0.102: J22.12 114.98,88.95 R249.1
IM1: length 3.8
  TOP w0.102: R255.1 114.55,89.45 J22.11
IM2: length 3.9
  TOP w0.102: J22.10 114.8,89.95 R248.1
INN1: length 2.9
  TOP w0.152: U17.33 63.09,84.95 63.02,85.03 63.02,85.85 62.53,86.34 62.53,86.73 C131.2
INN2: length 2.8
  TOP w0.152: U17.31 64.09,84.94 64.02,85.01 64.02,85.75 64.39,86.12 64.39,86.74 C133.2
INP1: length 2.9
  TOP w0.152: U17.34 62.59,84.92 62.66,84.99 62.66,85.7 62.17,86.19 62.17,86.73 C129.2
INP2: length 2.8
  TOP w0.152: U17.32 63.59,84.91 63.66,84.98 63.66,85.9 64.04,86.27 64.04,86.74 C132.2
IRCUT_IN1: length 4.3
  TOP w0.102: U21.2 57.18,12.77 TP62.1
IRCUT_IN2: length 5.9
  TOP w0.102: U21.3 56.17,12.27 TP63.1
KEY1_PB19: length 106.7
  TOP w0.102: U6.D16 68.03,51.83 69.18,51.83 69.97,52.62 93.66,52.62 94.12,53.08 95.4,53.08 v1(95.56,52.92) TP20.1 ; SW2.4 SW2.3 92.61,98.39 R288.1 92.61,86.78 v1(92.64,86.76)
  BOTTOM w0.102: v1(95.56,52.92) 95.77,53.13 95.77,70.38 96.99,71.61 103.68,71.61 104.81,70.48 108.25,70.48 109.42,71.65 109.42,76.43 99.1,86.76 v1(92.64,86.76)
LED0: length 45
  TOP w0.102: v1(76.12,17.99) 75.34,17.22 75.34,11.75 76.19,10.9 77.03,10.9 77.72,11.59 R246.1 ; U6.R13 66.31,44.26 66.31,43.74 66.72,43.32 66.72,43.1 68.75,41.07 69.76,41.07 70.33,40.5 70.33,39.74 70.16,39.57 70.16,37.6 70.43,37.34 70.43,32.17 79.12,23.48 v1(79.73,23.48)
  BOTTOM w0.102: v1(76.12,17.99) 76.3,18.18 76.3,20.42 79.35,23.48 v1(79.73,23.48)
LED1: length 44.9
  TOP w0.102: v1(79.22,23.9) 79.12,23.9 72.29,30.73 72.29,39.4 70.16,41.53 68.97,41.53 67.62,42.88 67.62,44.25 U6.R15 ; R299.1 78.49,11.27 77.84,10.61 75.99,10.61 75.1,11.51 75.1,17.98 v1(75.86,18.73)
  BOTTOM w0.102: v1(75.86,18.73) 75.86,20.53 v1(79.22,23.9)
LED2: length 3.5
  TOP w0.102: TP65.1 68.14,10.32 66.69,11.77 U21.21
LED11: length 4
  TOP w0.102: TP64.1 68.13,9.62 68.13,9.93 66.79,11.27 U21.20
LIN: length 3
  TOP w0.102: C130.2 60.98,86.49 62.09,85.37 U17.35
LR1: length 3.6
  TOP w0.33: 3.41,11.82 3.99,12.41 U13.2
  TOP w0.381: 3.41,11.82 2.44,11.82 R143.2 1.98,13.13 R129.2
LR2: length 3.7
  TOP w0.33: R146.2 90.1,2.22 90.1,3.21 89.46,3.84 U14.2
  TOP w0.381: R146.2 R130.2
LR3: length 3.9
  TOP w0.305: R149.2 101.31,91.85 101.31,91.17 101.96,90.52 U15.2
  TOP w0.381: R149.2 R131.2
LR4: length 5.3
  TOP w0.33: U16.2 15.88,61.96 15.29,62.55 15.29,63.02 15.53,63.26 17.23,63.26 R150.2
  TOP w0.381: R132.2 17.88,63.9 R150.2
M_F_A+: length 8
  TOP w0.249: 64.31,8.11 U21.14
  TOP w0.381: v1(64.31,7.36) 64.31,8.11
  TOP w0.508: v1(60.47,5.53) 60.45,5.51 J18.7
  BOTTOM w0.508: v1(60.47,5.53) 63.18,5.53 64.31,6.66 v1(64.31,7.36)
M_F_A-: length 10.5
  TOP w0.249: 65.31,8.38 U21.16
  TOP w0.381: v1(65.31,7.33) 65.31,8.38
  TOP w0.508: J18.8 v1(59.2,5.33)
  BOTTOM w0.508: v1(59.2,5.33) 59.69,4.85 63.46,4.85 65.31,6.69 v1(65.31,7.33)
M_F_B+: length 6.6
  TOP w0.249: 66.55,9.77 U21.17
  TOP w0.381: v1(66.9,7.25) 66.9,9.42 66.55,9.77
  TOP w0.508: J18.1 v1(67.95,5.49)
  BOTTOM w0.508: v1(67.95,5.49) 66.9,6.55 v1(66.9,7.25)
M_F_B-: length 7.7
  TOP w0.249: 67.21,10.07 66.51,10.77 U21.19
  TOP w0.381: 67.47,6.77 67.47,9.81 67.21,10.07
  TOP w0.508: 67.47,6.77 66.7,6 J18.2
M_OSCIN: length 1.5
  TOP w0.102: R209.2 67.19,13.27 U21.24
M_OSCOUT: length 1.5
  TOP w0.102: U21.23 67.21,12.77 R211.2
M_RSTB: length 15.1
  TOP w0.102: v1(58.97,15.24) 59.06,15.14 C167.1 59.07,14.27 R204.2 59.15,13.27 U21.1 ; R72.2 v1(66.74,18.08)
  BOTTOM w0.102: v1(66.74,18.08) 66.63,17.99 61.72,17.99 v1(58.97,15.24)
M_VD_FZ: length 13.2
  TOP w0.102: U21.30 62.81,15.93 62.96,16.07 62.95,16.08 v1(62.95,16.24) ; v1(69.74,16.61) 69.74,19.32 69.47,19.59 R75.2
  BOTTOM w0.102: v1(62.95,16.24) 63.32,16.61 v1(69.74,16.61)
M_Z_A+: length 8.5
  TOP w0.249: U21.8 60.84,9.77 60.4,9.32
  TOP w0.508: J18.5 v1(62.95,6.21) ; v1(60.4,6.24) 60.4,9.32
  BOTTOM w0.508: v1(60.4,6.24) 62.92,6.24 v1(62.95,6.21)
M_Z_A-: length 5
  TOP w0.249: U21.10 62.31,8.03
  TOP w0.381: 61.7,6.33 61.7,7.27 62.31,7.87 62.31,8.03
  TOP w0.508: 61.7,6.33 J18.6
M_Z_B+: length 5.4
  TOP w0.249: U21.11 62.81,8.02
  TOP w0.381: 62.81,8.02 62.81,7.21
  TOP w0.508: 62.81,7.21 64.2,5.82 J18.4
M_Z_B-: length 5.5
  TOP w0.249: 63.81,8.04 U21.13
  TOP w0.381: 64.22,6.75 63.81,7.16 63.81,8.04
  TOP w0.508: 64.22,6.75 65.45,5.51 J18.3
MDI_RN: length 3.6
  TOP w0.102: R219.2 93.12,19.94 U23.1
MDI_RP: length 3.6
  TOP w0.102: R216.2 93.12,17.4 U23.3
MDI_TN: length 3.6
  TOP w0.102: U23.6 93.12,13.59 R214.2
MDI_TP: length 3.6
  TOP w0.102: U23.8 93.12,11.05 R238.2
MDVDD: length 3.5
  TOP w0.254: U21.25 v1(65.31,14.66)
  BOTTOM w0.381: C174.1 65.74,14.23 v1(65.31,14.66) 65.3,14.66 C173.1 64.69,14.12 R201.1
MICBIAS: length 61.4
  TOP w0.254: U6.P3 v1(59.16,44.91)
  TOP w0.305: v1(51.28,44.25) 36.86,29.82 32.03,29.82 14.76,12.56 R94.2
  BOTTOM w0.254: C86.1 56.74,45.38 C85.1 58.11,44.91 v1(59.16,44.91)
  BOTTOM w0.305: v1(51.28,44.25) 53.21,46.17 55.94,46.17 C86.1
MICN1: length 22.8
  TOP w0.152: C131.1 62.53,88.32 62.53,89.58 60.19,91.91 55.97,91.91 53.41,94.47 53.41,95.11 R176.1 53.41,95.55 53.41,95.95 R178.1 53.4,96.63 53.4,96.92 C144.1 53.38,97.62 53.38,97.69 53.38,98.04 D11.2 53.36,98.55 53.36,102.02 53.81,102.47 J13.1
MICN2: length 17.2
  TOP w0.152: J14.1 63.26,102.55 62.82,102.1 62.82,98.47 D13.2 62.81,98.13 62.82,97.61 C145.1 62.84,96.9 62.84,96.66 R179.1 62.84,95.99 62.84,95.59 R177.1 62.86,95.23 62.86,92.09 64.39,90.56 64.39,88.21 64.54,88.06 C133.1
MICNL: length 63.5
  TOP w0.152: J9.1 19.56,4.94 19.11,5.39 19.11,5.96 D7.2 19.1,6.54 19.09,7.11 19.09,7.32 C104.1 19.16,7.93 19.16,8.44 19.32,8.6 R90.1 19.08,8.85 19.08,9.16 v1(19.19,9.27) 19.09,9.38 19.09,12.62 34.62,28.14 37.64,28.14 49.96,40.46 50.21,40.46 50.49,40.18 50.75,40.18 50.93,40.36 50.93,40.61 50.65,40.89 50.65,41.14 50.82,41.32 51.08,41.32 51.36,41.04 51.61,41.04 51.79,41.22 51.79,41.47 51.51,41.76 51.51,42.01 51.69,42.19 51.94,42.19 52.22,41.91 52.47,41.91 52.65,42.08 52.65,42.34 52.37,42.62 52.37,42.87 53.29,43.79 53.6,43.79 C66.2
  BOTTOM w0.152: v1(19.19,9.27) 19.09,9.17 19.09,8.87 19.24,8.72 21.65,8.72 R313.2
MICP1: length 22.8
  TOP w0.152: C129.1 62.17,88.32 62.17,89.43 60.04,91.56 55.82,91.56 53.05,94.32 53.05,95.11 R180.2 53.05,95.55 53.05,95.94 R178.2 53.05,96.63 53.05,96.91 C144.2 53.02,97.58 53.02,97.73 53.02,98.04 D10.2 53.01,98.52 53.01,102.02 52.56,102.47 J13.2
MICP2: length 17.2
  TOP w0.152: C132.1 64.04,88.34 64.04,90.42 62.51,91.94 62.51,95.15 R181.2 62.48,95.62 62.48,95.98 R179.2 62.48,96.68 62.48,96.91 C145.2 62.47,97.57 62.46,98.12 D12.2 62.46,98.47 62.46,102.1 62.01,102.55 J14.2
MICPL: length 61.4
  TOP w0.152: J9.2 18.31,4.98 18.74,5.41 18.74,5.95 D6.2 18.74,6.53 18.74,7.31 C104.2 18.68,7.94 18.68,8.45 R91.2 18.72,8.8 18.72,9.19 v1(18.63,9.27) 18.74,9.38 18.74,12.76 34.47,28.5 37.5,28.5 53.16,44.16 53.59,44.16 C65.2
  BOTTOM w0.152: R97.2 21.65,8.36 19.09,8.36 18.74,8.72 18.74,9.17 v1(18.63,9.27)
MINNL: length 5.5
  TOP w0.102: U6.P2 58.71,45.23 58.4,44.94 57.84,44.94 56.79,43.88 56.35,43.88 56.27,43.81 56.25,43.81
  TOP w0.152: 56.25,43.81 55.85,43.81 55.68,43.64 55.68,43.16 55.53,43 55.11,43 54.91,43.21 C66.1
MINPL: length 5.5
  TOP w0.102: 56.25,44.16 56.27,44.16 56.35,44.09 56.7,44.09 57.76,45.14 58.31,45.14 58.73,45.56 59.16,45.56 U6.N3
  TOP w0.152: C65.1 55.19,44.16 56.25,44.16
MIPI_DVP_IRCUTN_PB18: length 163.4
  TOP w0.102: J11.31 v1(24.27,44.57) ; v1(97.96,69.53) 97.83,69.65 v1(83.91,69.65) ; U6.E17 68.65,51.01 101.38,51.01 v1(101.89,51.52) TP19.1 ; v1(41.71,36.52) J12.25 29.78,36.52 v1(29.74,36.57)
  BOTTOM w0.102: v1(41.71,36.52) 46.51,41.32 46.51,60.76 49.81,64.06 62.23,64.06 63.01,64.83 64.77,64.83 65.25,65.31 73.03,65.31 77.38,69.65 v1(83.91,69.65) ; v1(24.27,44.57) 24.28,44.56 24.53,44.56 29.44,39.65 29.44,36.87 v1(29.74,36.57) ; v1(101.89,51.52) 101.75,51.39 100.5,51.39 97.96,53.93 v1(97.96,69.53)
MIPI_DVP_IRCUTP_PB17: length 164.5
  TOP w0.102: v1(83.2,70.01) v1(98.26,70.01) ; v1(29.82,37.11) 29.91,37.02 J12.24 v1(41.51,37.02) ; TP18.1 v1(100.6,51.79) 100.08,51.27 94.28,51.27 93.41,52.13 70.11,52.13 69.37,51.39 68.4,51.39 68.1,51.08 U6.E16 ; J11.32 v1(23.73,45.07)
  BOTTOM w0.102: v1(83.2,70.01) 77.42,70.01 72.99,65.58 65.06,65.58 64.66,65.17 63,65.17 62.13,64.3 49.7,64.3 46.22,60.82 46.22,41.41 41.84,37.02 v1(41.51,37.02) ; v1(29.82,37.11) 29.76,37.17 29.76,39.64 24.32,45.07 v1(23.73,45.07) ; v1(100.6,51.79) 98.37,54.03 98.37,69.91 v1(98.26,70.01)
MIPI_DVP_MCLK: length 3.7
  TOP w0.102: R50.1 39.75,57.44 TP42.1 39.18,58.01 37.89,58.01 R125.1
MIPI_DVP_PWDN_PA19: length 56.4
  TOP w0.102: J11.25 24.32,41.57 v1(25.59,42.84) ; v1(22.99,45.56) 23.02,45.59 24.46,45.59 25.87,47 25.87,52.41 32.45,58.99 39.61,58.99 R229.1 ; v1(29.12,36.66) 29.75,36.02 J12.26 37.71,36.02 37.93,36.25 40.78,36.25 TP44.1
  BOTTOM w0.102: v1(22.99,45.56) 22.99,45.23 24.03,44.18 24.47,44.18 25.59,43.07 v1(25.59,42.84) 25.94,42.84 29.12,39.67 v1(29.12,36.66)
MIPI_DVP_RESET: length 68.3
  TOP w0.102: J11.33 20.51,45.57 20.98,46.04 24.23,46.04 v1(24.59,46.4) 25.64,47.45 25.64,52.65 32.22,59.23 42.26,59.23 44.14,57.35 TP43.1 44.36,57.07 50.7,50.72 55.93,50.72 56.8,51.59 57.74,51.59 57.75,51.6 58.5,51.6 58.68,51.42 59.15,51.42 U6.E3 ; J12.18 30.01,40.02 v1(29.77,40.26)
  BOTTOM w0.102: v1(24.59,46.4) 24.59,45.2 29.52,40.26 v1(29.77,40.26)
MIPI_MCLK_PA15: length 25
  TOP w0.102: J12.22 39.64,38.02 TP46.1 v1(40.56,38.02) ; R125.2 v1(38.98,57.45)
  BOTTOM w0.102: v1(38.98,57.45) 38.98,50.78 41.33,48.43 41.33,41.08 40.41,40.16 40.41,38.17 v1(40.56,38.02)
MIPI_RX_2LANE_CLKN0: length 10.1
  TOP w0.102: R118.2 v1(40.61,43.77) ; v1(35.97,47.77) 36.22,48.02 J12.2
  BOTTOM w0.102: v1(35.97,47.77) 35.84,47.91 35.84,48.11 35.94,48.21 36.65,48.21 37.3,47.56 37.3,46.53 37.53,46.3 37.53,46.13 37.52,46.13 37.52,45.96 37.64,45.84 37.81,45.84 37.82,45.84 37.99,45.84 38.1,45.73 38.1,45.56 38.1,45.55 38.1,45.38 38.22,45.26 38.39,45.26 38.39,45.27 38.56,45.27 39.55,44.28 40.5,44.28 40.61,44.18 v1(40.61,43.77)
MIPI_RX_2LANE_CLKP0: length 10.1
  TOP w0.102: v1(35.44,47.77) 35.19,47.52 J12.3 ; R116.2 v1(40.61,45.06)
  BOTTOM w0.102: v1(40.61,45.06) 40.61,44.66 40.5,44.56 39.67,44.56 37.58,46.65 37.58,47.68 36.77,48.49 35.82,48.49 35.56,48.22 35.56,47.89 v1(35.44,47.77)
MIPI_RX_2LANE_DN0: length 12
  TOP w0.102: J12.5 37.77,46.52 38.23,46.98 38.23,49.32 38.59,49.69 39.79,49.69 40.36,49.11 40.36,47.34 40.55,47.15 41.08,47.15 41.18,47.25 R110.2
MIPI_RX_2LANE_DN1: length 9.7
  TOP w0.102: J12.8 36.22,45.02 v1(35.97,44.77) ; R114.2 v1(40.61,41.28)
  BOTTOM w0.102: v1(40.61,41.28) 40.61,41.66 40.5,41.76 38.08,41.76 37.08,42.76 37.08,43.19 36.96,43.31 36.76,43.31 36.65,43.43 36.65,43.6 36.76,43.72 36.96,43.72 37.08,43.84 37.08,44.36 36.58,44.86 36.06,44.86 v1(35.97,44.77)
MIPI_RX_2LANE_DP0: length 12
  TOP w0.102: R108.2 41.18,46.75 41.06,46.87 40.44,46.87 40.08,47.22 40.08,49 39.67,49.41 38.71,49.41 38.51,49.21 38.51,48.76 38.63,48.64 39.18,48.64 39.3,48.52 39.3,48.35 39.18,48.23 38.63,48.23 38.51,48.11 38.51,47.94 38.63,47.82 39.18,47.82 39.3,47.71 39.3,47.54 39.18,47.42 38.63,47.42 38.51,47.3 38.51,46.86 37.67,46.02 J12.6
MIPI_RX_2LANE_DP1: length 9.7
  TOP w0.102: J12.9 35.19,44.52 v1(35.44,44.77) ; R112.2 v1(40.61,42.52)
  BOTTOM w0.102: v1(35.44,44.77) 35.81,45.14 36.7,45.14 37.36,44.47 37.36,42.88 38.2,42.04 40.5,42.04 40.61,42.14 v1(40.61,42.52)
MSC0_CLK_PB04: length 8.8
  TOP w0.102: R43.2 103.26,38.74 TP61.1 103.29,38.71 J16.5
MSC0_CMD_PB05: length 45.9
  TOP w0.102: U6.G17 68.62,49.75 90.82,49.75 100.24,40.34 TP60.1 106.12,40.34 R197.2 110.29,40.91 J16.3
MSC0_D0_PB00: length 48
  TOP w0.102: J16.7 110.29,36.5 R193.2 106.17,36 TP56.1 101.24,36 88.11,49.13 U6.H16
MSC0_D1_PB01: length 49.2
  TOP w0.102: U6.J15 67.63,48.82 88.01,48.82 101.97,34.87 TP57.1 106.12,34.87 R194.2 110.28,35.42 J16.8
MSC0_D2_PB02: length 46.6
  TOP w0.102: J16.1 106.7,43.11 R195.2 106.17,42.61 103.21,42.61 TP58.1 98.81,42.6 91.1,50.31 68.31,50.31 68.11,50.11 67.61,50.11 U6.G15
MSC0_D3_PB03: length 46.3
  TOP w0.102: J16.2 110.29,42.02 R196.2 106.19,41.5 101.49,41.5 TP59.1 99.54,41.52 90.97,50.09 68.46,50.09 68.16,49.78 U6.G16
MVCCA: length 8.4
  TOP w0.249: U21.15 v1(64.81,8.32)
  BOTTOM w0.508: R202.1 63.24,7.44 63.92,8.13 63.92,8.63 C169.1 64.29,8.83 v1(64.81,8.32) 65.28,8.79 C170.1
MVCCB: length 4.1
  TOP w0.249: U21.9 v1(61.81,8.32)
  BOTTOM w0.508: R205.1 61.12,8.93 C171.1 61.74,8.32 v1(61.81,8.32) 62.13,8.64 C172.1
OSC32_XI: length 9.2
  TOP w0.102: U6.M16 68.03,46.44 70.13,46.44 70.71,45.86 72.72,45.86 R23.2 73.69,46.1 74.3,46.71 Y1.2 76.22,46.71 C57.2
OSC32_XO: length 10.2
  TOP w0.102: C58.2 76.26,44.21 Y1.1 74.31,44.21 73.46,45.06 R23.1 72.46,45.56 70.58,45.56 69.94,46.2 67.62,46.2 U6.M15
OUT2_R: length 4
  TOP w0.102: U17.26 69.71,82.88 TP48.1
OUT3_MIXER: length 2.3
  TOP w0.102: U17.27 68.71,83.38 TP49.1
OUTE1: length 5.7
  TOP w0.102: TP66.1 56.72,10.27 U21.7
OUTE2: length 3.9
  TOP w0.102: TP69.1 57.25,11.27 U21.5
PHY_ACTA: length 38.8
  TOP w0.102: v1(76.68,11.28) R246.2 76.68,12.84 R245.2
  BOTTOM w0.102: v1(76.68,11.28) 76.68,11.25 79.53,8.4 92.67,8.4 99.51,1.57 106.91,1.57 107.56,2.22 107.56,3.05 R224.2
PHY_LED0: length 3.6
  TOP w0.102: U22.24 v1(78.58,13.7) R245.1
  BOTTOM w0.102: R315.1 78.66,13.78 v1(78.58,13.7) 78.5,13.78 R314.2
PHY_LED1: length 3.5
  TOP w0.102: R247.1 80.22,11.71 v1(80.22,11.89) U22.25
  BOTTOM w0.102: R317.1 80.41,11.71 v1(80.22,11.89) 80.22,12.77 R316.2
PHY_LINKA: length 45.4
  TOP w0.102: v1(78.24,10.23) 78.24,10.23 R299.2 78.87,10.24 R247.2
  BOTTOM w0.102: R231.2 107.4,27.49 93.57,27.49 87.79,21.71 87.79,13.19 83.21,8.61 79.86,8.61 v1(78.24,10.23)
PHY_NRST: length 9.3
  TOP w0.102: R287.1 68.79,36.88 68.79,37.75 R56.1 C96.1 68.74,39.55 68.74,40.72 66.32,43.14 66.32,43.4 65.99,43.73 U6.T13
PLL_AVDD18: length 5
  TOP w0.254: U6.D3 v1(59.16,52.06)
  BOTTOM w0.305: C56.1 58.08,53.67 58.67,53.08 58.67,52.5 59.11,52.06 v1(59.16,52.06)
  BOTTOM w0.381: FB3.2 55.92,54.15 56.61,54.15 C55.1 57.08,53.68 58,53.68 C56.1
POR_CTRL: length 5
  TOP w0.102: U6.K16 68.03,47.74 69.46,47.74 v1(69.76,47.44)
  BOTTOM w0.102: v1(69.76,47.44) 69.94,47.44 70.19,47.69 71.28,47.69 R29.2 72.51,48.15 R30.2
PPRST_N: length 114.3
  TOP w0.102: v1(79.91,41.19) 79.91,47.12 79.27,47.76 71.03,47.76 70.33,47.06 69.61,47.06 69.15,47.52 68.27,47.52 U6.L16 ; v1(49.13,52.95) 48.89,52.95 46.16,55.69 46.16,58.75 43.68,61.23 25.56,61.23 19.37,67.41 U8.2 14.01,67.41 R34.2
  BOTTOM w0.102: v1(49.13,52.95) 48.55,52.37 48.55,38.54 52.94,34.15 72.28,34.15 79.32,41.19 v1(79.91,41.19)
PULSE1: length 2.6
  TOP w0.102: TP67.1 62.31,15.8 U21.31
PULSE2: length 3
  TOP w0.102: U21.32 61.81,14.17 59.94,16.04 TP68.1
PWRON: length 19.6
  TOP w0.102: U6.K15 67.63,48.18 68.05,48.18 68.25,47.97 79.42,47.97 80.76,46.64 80.76,42.85 TP9.1
RD_N: length 39.9
  TOP w0.102: U6.U17 68.78,43.48 68.91,43.48 69.41,42.98 71.09,42.98 91.12,22.94 91.12,21.16 v1(91,21.03) ; R244.1 v1(93.93,19.12)
  BOTTOM w0.102: v1(93.93,19.12) 93.61,18.81 93.14,18.81 92.74,19.22 92.74,21.33 92.16,21.9 91.43,21.9 91.11,21.58 91.11,21.14 v1(91,21.03)
RD_P: length 39.9
  TOP w0.102: R242.1 v1(93.93,18.22) ; U6.T17 68.76,43.76 69.02,43.76 69.52,43.26 71.21,43.26 91.4,23.06 91.4,21.16 v1(91.53,21.03)
  BOTTOM w0.102: v1(93.93,18.22) 93.61,18.53 93.03,18.53 92.46,19.1 92.46,21.21 92.05,21.63 91.55,21.63 91.39,21.46 91.39,21.17 v1(91.53,21.03)
RMII_MDCK: length 7.2
  TOP w0.102: U6.R10 64.37,44.25 64.37,41.89 65.56,40.7 65.56,38.89 R49.1
RMII_MDIO: length 4.1
  TOP w0.102: U6.T10 64.04,41.67 64.97,40.74 R51.1
RMII_PHY_CLK: length 4.1
  TOP w0.102: R47.1 63.85,40.86 63.34,41.38 63.34,42.74 63.04,43.03 63.04,43.43 63.39,43.78 U6.T9
RMII_TX0: length 5.4
  TOP w0.102: R52.1 67.26,40.51 65.21,42.56 65.21,43.57 65,43.78 65,44.27 U6.R11
RMII_TX1: length 6.7
  TOP w0.102: R53.1 66.17,38.35 66.65,38.84 66.65,40.55 65,42.2 65,43.42 64.69,43.73 U6.T11
RMII_TXEN: length 3.7
  TOP w0.102: U6.U11 64.69,42.01 66.18,40.52 R48.1
RST_OUT: length 17.6
  TOP w0.102: TP7.1 80.97,44.11 80.97,46.72 79.51,48.18 68.44,48.18 68.14,48.48 U6.J16
RTC_0V8: length 15
  BOTTOM w0.381: U26.5 88.95,45.58 C208.1 87.23,44.99 TP70.1 87.01,45.19 76.39,45.19 R294.2
RTC_1V8: length 22.7
  TOP w0.381: U25.5 88.83,55.71 C206.1 v1(89.23,54.73)
  BOTTOM w0.381: R323.2 83.48,45.72 R285.1 87.72,49.69 U26.1 88.95,51.64 C207.1 88.96,54.45 v1(89.23,54.73)
RTC_IRQ_N: length 12.7
  TOP w0.102: v1(68.95,66.56) R68.2 68.06,65.8 R46.1
  BOTTOM w0.102: U27.3 75,72.57 73.38,70.96 R305.1 73.38,69.14 70.8,66.56 v1(68.95,66.56)
RX+: length 18.6
  TOP w0.254: J19.3 117.35,16.72 116.44,15.82 116.44,14.89 116.57,14.76 116.57,13.73 116.07,13.22 114.66,13.22 109.42,18.46 106.98,18.46 105.92,17.4 U23.14
RX-: length 18.7
  TOP w0.254: J19.6 114.42,14.23 113.36,15.29 113.36,15.71 114.15,16.5 114.15,16.93 113.86,17.22 113.44,17.22 112.64,16.43 112.22,16.43 111.93,16.73 111.93,17.15 112.72,17.94 112.72,18.36 112.42,18.66 112,18.66 111.21,17.87 110.79,17.87 109.58,19.08 106.98,19.08 106.11,19.94 U23.16
RX_DV: length 4.9
  TOP w0.102: U6.P14 v1(66.96,44.91)
  BOTTOM w0.102: v1(66.96,44.91) 66.59,44.54 66.59,41.31 R57.1
RX_N1: length 8.1
  TOP w0.102: U22.6 84.68,16.2 84.79,16.09 87.68,16.09 90.4,18.81 90.95,18.81 R219.1
RX_P1: length 8.1
  TOP w0.102: U22.5 84.66,15.7 84.77,15.81 87.8,15.81 90.52,18.53 90.95,18.53 R216.1
RXD3: length 2.6
  TOP w0.102: U6.R14 v1(66.31,44.91)
  BOTTOM w0.102: v1(66.31,44.91) 66.31,43.95 R58.1 66.09,43.73 R59.1
RXDV: length 3.5
  TOP w0.102: R227.2 86.33,17.83 v1(86.23,17.73) 85.7,17.2 U22.8
  BOTTOM w0.102: v1(86.23,17.73) 86.25,17.73 R230.1
SD0_CD_N_PB27: length 81.1
  TOP w0.102: R192.1 v1(107.31,34.3) 110.29,34.3 J16.9 ; R54.1 v1(66.13,66.39) ; v1(84.41,70.41) v1(98.86,70.41)
  BOTTOM w0.102: R237.1 107.59,34.02 v1(107.31,34.3) 107.21,34.4 107.21,47.02 102.27,51.96 100.97,51.96 98.65,54.28 98.65,70.2 v1(98.86,70.41) ; v1(84.41,70.41) 77.44,70.41 72.9,65.87 68.01,65.87 67.19,66.69 66.42,66.69 v1(66.13,66.39)
SD_CLK: length 37.8
  TOP w0.102: U6.H15 67.6,49.45 89.27,49.45 99.99,38.74 R43.1
SD_PWR_EN_N: length 55.9
  TOP w0.102: v1(100.45,53.12) 100.45,52.23 99.74,51.52 95.26,51.52 TP21.1 94.41,52.37 70.05,52.37 69.29,51.62 68.29,51.62 68.08,51.4 67.61,51.4 U6.E15
  BOTTOM w0.102: v1(100.45,53.12) 101.18,52.39 102.43,52.39 107.49,47.32 107.49,37.47 107.94,37.02 107.94,36.79 107.94,36.79 R239.1
SDIN1: length 1.6
  TOP w0.254: U17.5 v1(59.62,81.38)
  BOTTOM w0.102: R162.2 59.62,81.37 v1(59.62,81.38)
SDIO_WIFI_CLK_PC02: length 58.9
  TOP w0.102: v1(79.54,66.12) 79.54,66.53 80.71,67.7 98.92,67.7 103.89,62.73 J17.24 ; R45.1 v1(55.21,59.95)
  BOTTOM w0.102: v1(55.21,59.95) 55.84,60.57 68.96,60.57 70.22,61.83 72.53,61.83 77.28,66.58 79.09,66.58 v1(79.54,66.12)
SDIO_WIFI_CMD_PC03: length 55.4
  TOP w0.102: J17.34 98.89,59.97 97.88,60.97 97.88,65.15 96.35,66.68 80.51,66.68 80.35,66.52 v1(80.35,66.12) ; R309.2 v1(53.94,59.95)
  BOTTOM w0.102: v1(80.35,66.12) 79.55,66.92 77.15,66.92 72.38,62.14 70.19,62.14 68.84,60.8 54.79,60.8 v1(53.94,59.95)
SDIO_WIFI_D0_PC04: length 55.3
  TOP w0.102: v1(78.98,66.09) 78.98,66.31 80.62,67.96 99.1,67.96 104.39,62.67 J17.23 ; R311.2 v1(56.43,59.91)
  BOTTOM w0.102: v1(78.98,66.09) 78.95,66.12 77.23,66.12 72.67,61.56 70.25,61.56 68.97,60.28 56.8,60.28 v1(56.43,59.91)
SDIO_WIFI_D1_PC05: length 49.5
  TOP w0.102: v1(57.36,59.88) 57.49,60.02 R318.2 ; J17.35 98.39,65.05 96.5,66.94 80.35,66.94 79.9,66.49 79.9,65.53 v1(79.88,65.5)
  BOTTOM w0.102: v1(79.88,65.5) 79.75,65.62 77.14,65.62 72.82,61.31 70.32,61.31 69.04,60.04 57.51,60.04 v1(57.36,59.88)
SDIO_WIFI_D2_PC06: length 56.5
  TOP w0.102: v1(52.15,59.95) 52.05,60.04 R319.2 ; v1(80.86,67.34) 98.72,67.34 99.39,66.67 J17.33
  BOTTOM w0.102: v1(52.15,59.95) 52.15,60.04 53.37,61.26 68.48,61.26 69.92,62.7 72.17,62.7 77.1,67.63 80.57,67.63 v1(80.86,67.34)
SDIO_WIFI_D3_PC07: length 55.4
  TOP w0.102: J17.36 97.89,59.97 96.95,60.9 96.95,65.61 96.16,66.39 80.97,66.39 v1(80.89,66.31) ; R320.2 v1(53.01,59.94)
  BOTTOM w0.102: v1(80.89,66.31) 79.9,67.3 77.09,67.3 72.23,62.43 70.07,62.43 68.67,61.03 54.1,61.03 v1(53.01,59.94)
SDIO_WIFI_EN_PC09: length 63.7
  TOP w0.102: U6.C6 61.12,52.7 61.12,54.01 61.46,54.35 61.46,59.33 v1(61.12,59.66) ; J17.16 107.89,59.69 107.39,60.19 105.46,60.19 104.89,60.76 104.89,62.67 99.3,68.26 80.63,68.26 78.05,65.68 v1(78.05,65.27)
  BOTTOM w0.102: v1(61.12,59.66) 61.28,59.82 69.16,59.82 70.36,61.02 73,61.02 77.24,65.27 v1(78.05,65.27)
SDOUT2: length 2.9
  TOP w0.102: TP51.1 63.29,76.32 64.09,77.12 U17.15
SDOUT3: length 4.9
  TOP w0.102: TP52.1 62.6,74.84 62.6,76.16 63.59,77.15 U17.14
SFC1_CE: length 26.2
  TOP w0.102: U6.R7 61.77,44.26 61.77,43.77 61.52,43.52 61.52,43.1 61.72,42.89 61.72,29.16 64.44,26.44 64.44,24.81 63.35,23.72 63.35,21.75 R124.1 63.81,21.31 R123.1
SFC1_CLK: length 23.4
  TOP w0.102: U6.T8 62.61,43.81 62.61,29.84 67.61,24.85 R121.1 68.4,23.47 R120.1
SFC1_CS_N: length 18.5
  TOP w0.102: R124.2 63.44,20.26 v1(63.32,20.38)
  BOTTOM w0.102: R78.1 52.07,18.86 51.4,19.54 U28.1 52.83,20.85 53.38,21.41 62.3,21.41 v1(63.32,20.38)
SFC1_DR_IO1: length 22.9
  TOP w0.102: R67.1 64.46,23.49 64.46,23.49 64.03,23.49 ; 64.03,23.49 R87.1 ; 64.03,23.49 64.68,24.15 64.68,26.59 61.97,29.31 61.97,42.97 61.75,43.19 61.75,43.42 62.09,43.75 U6.T7
SFC1_DT_IO0: length 23.6
  TOP w0.102: R82.1 66.44,23.42 66.44,23.42 66.01,23.42 ; 66.01,23.42 66.01,26.1 62.4,29.72 62.4,44.25 U6.R8 ; 66.01,23.42 R85.1
SFC1_HD_IO3: length 26.9
  TOP w0.102: R165.1 69.47,21.48 R75.1 69.47,23.35 62.83,30 62.83,43.58 63.06,43.81 63.06,44.26 U6.R9
SFC1_SCLK: length 10.4
  TOP w0.102: R121.2 67.61,21.94 v1(67.6,21.94)
  BOTTOM w0.102: U28.6 63.79,23.39 65.7,21.48 67.15,21.48 v1(67.6,21.94)
SFC1_SIO0: length 8.8
  TOP w0.102: v1(65.91,21.93) 65.96,21.98 R85.2
  BOTTOM w0.102: U28.5 63.18,24.66 v1(65.91,21.93)
SFC1_SIO1: length 13.2
  TOP w0.102: R87.2 63.73,22.2 v1(63.73,21.99)
  BOTTOM w0.102: v1(63.73,21.99) 63.46,21.72 52.54,21.72 52.14,22.12 U28.2
SFC1_SIO2: length 16.3
  TOP w0.102: R167.2 65.91,20.27 v1(65.52,20.66)
  BOTTOM w0.102: v1(65.52,20.66) 65.22,20.66 64.76,21.12 64.76,21.94 63.83,22.87 52.59,22.87 52.07,23.39 U28.3
SFC1_SIO3: length 12
  TOP w0.102: v1(68.16,19.94) 68.65,20.44 R165.2
  BOTTOM w0.102: v1(68.16,19.94) 65.23,19.94 64.44,20.73 64.44,21.86 63.89,22.41 63.45,22.41 63.2,22.15 58.72,22.15 U28.7
